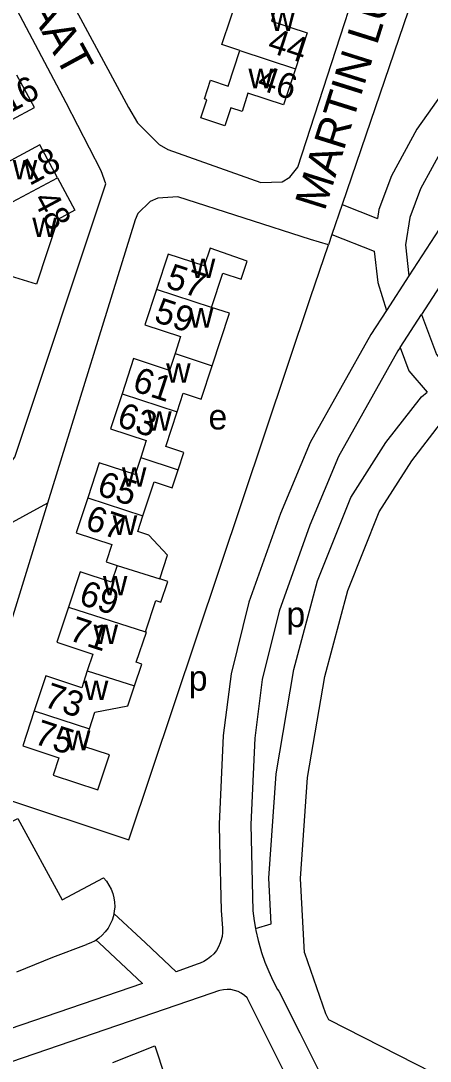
# Model space of a CAD drawing. Extents: x 157794 to 159375, y 380877 to 382306.
# Drawn here: x 159054.3 to 159118.9, y 381731.3 to 381895.6 of the extents above; entities that cross this region are included whole.
import ezdxf

# ---------------------------------------------------------------- set-up
doc = ezdxf.new("R2010")
doc.units = 0
for name, color, linetype in [('BLT_Basislijn', 7, 'Continuous'), ('BLT_Bebouwing', 7, 'Continuous'), ('BLT_Centroide', 7, 'Continuous'), ('BLT_Huisnummer', 7, 'Continuous'), ('BLT_Huisnummer_ tussenligend', 7, 'Continuous'), ('BLT_Onderverdeling_panden', 7, 'Continuous'), ('BLT_Straatnaam', 7, 'Continuous')]:
    doc.layers.add(name, color=color, linetype=linetype)

msp = doc.modelspace()

# ---------------------------------------------------------------- linework, layer by layer
at = {"layer": 'BLT_Basislijn'}
for p, q in [((159131.04, 381942.86), (159105.03, 381866.63)), ((159105.03, 381866.63), (159103.41, 381861.89)), ((159105.03, 381866.63), (159110.6, 381864.42)), ((159103.41, 381861.89), (159102.86, 381860.28)), ((159103.41, 381861.89), (159110.09, 381859.24)), ((159115.55, 381855.37), (159112.01, 381849.89)), ((159114.17, 381844.04), (159117.55, 381849.26)), ((159058.47, 381819.44), (159047.17, 381813.34)), ((159045.25, 381774.98), (159071.3, 381766.29)), ((159068.97, 381754.68), (159073.96, 381750)), ((159091.33, 381752.31), (159093.8, 381753.02)), ((159059.32, 381747.74), (159064.64, 381749.75)), ((159065.3, 381750), (159064.64, 381749.75)), ((159066.15, 381750.47), (159066.65, 381750)), ((159066.65, 381750), (159073.46, 381743.61)), ((159073.96, 381750), (159078.81, 381745.44)), ((159053.63, 381745.42), (159059.32, 381747.74)), ((159082.12, 381746.66), (159078.81, 381745.44)), ((159073.46, 381743.61), (158994.46, 381716.52)), ((159068.77, 381731.14), (159075.44, 381733.75))]:
    msp.add_line(p, q, dxfattribs=at)
for points in [[(159024.73, 381972.06), (159024.29, 381971.41), (159023.98, 381970.76), (159023.95, 381970.05), (159024.07, 381969.44), (159071.25, 381881.93), (159072.69, 381879.52), (159076.12, 381876.12), (159077.49, 381875.32), (159092.19, 381870.11), (159095.54, 381870.21), (159096.74, 381870.93), (159098.02, 381872.52), (159100, 381878.71), (159111.44, 381913.93), (159114.91, 381926.43), (159120.96, 381946.35)], [(158994.07, 381923.44), (158982.1, 381906.19), (158981.46, 381904.6), (158981.34, 381899.92), (158982.25, 381897.5), (159026.42, 381815.66), (159028.37, 381813.47), (159029.25, 381813.04), (159032.7, 381813.07), (159049.22, 381822.15), (159051.23, 381824.01), (159053.32, 381826.75), (159067.69, 381869.91), (159066.93, 381871.95), (159061.42, 381882.67), (159029.46, 381943.09)], [(159128.38, 381896.12), (159126.57, 381892.41), (159123.16, 381887.51), (159116.8, 381878.51), (159112.81, 381871.18), (159110.82, 381865.87), (159110.6, 381864.42)], [(159132.83, 381893.83), (159130.9, 381889.87), (159127.26, 381884.64), (159121.05, 381875.86), (159117.37, 381869.09), (159115.68, 381864.59), (159115.01, 381860.27), (159115.55, 381855.37)], [(159134.86, 381888.8), (159128.5, 381875.17), (159120.33, 381862.74), (159115.55, 381855.37)], [(159139.39, 381886.69), (159132.88, 381872.73), (159124.51, 381860.01), (159117.55, 381849.26)], [(159102.86, 381860.28), (159100, 381861.13), (159079.08, 381867.85), (159075.89, 381867.66), (159074.69, 381867.11), (159072.76, 381865.19), (159072.3, 381864.19), (159058.47, 381819.44)], [(159071.3, 381766.29), (159100, 381851.94), (159102.86, 381860.28)], [(159110.09, 381859.24), (159110.64, 381854.29), (159112.01, 381849.89)], [(159112.01, 381849.89), (159109.55, 381846.11), (159099.94, 381829.05), (159095.27, 381817.81), (159090.3, 381803.83), (159087.48, 381792.53), (159086.22, 381782.78), (159085.6, 381768.79), (159085.66, 381765.88)], [(159117.55, 381849.26), (159119.92, 381842.95), (159122.4, 381840.03)], [(159114.17, 381844.04), (159113.83, 381843.52), (159104.45, 381826.85), (159099.93, 381816.01), (159095.09, 381802.38), (159092.4, 381791.6), (159091.21, 381782.35), (159090.6, 381768.73), (159090.93, 381755.09)], [(159114.17, 381844.04), (159115.55, 381840.37), (159118.44, 381836.98)], [(159093.8, 381753.02), (159093.41, 381760.23), (159094.57, 381776.73), (159097.41, 381793.18), (159101.14, 381807.22), (159106.37, 381820.37), (159111.94, 381829.04), (159117.53, 381836.27), (159118.44, 381836.98)], [(159099.06, 381748.46), (159098.42, 381760.19), (159099.54, 381776.13), (159102.3, 381792.11), (159105.9, 381805.65), (159110.84, 381818.08), (159116.03, 381826.15), (159121.09, 381832.71), (159121.73, 381833.2)], [(159058.47, 381819.44), (159051.31, 381796.18), (159045.25, 381774.98)], [(159046.43, 381770.08), (159048.11, 381766.89), (159053.77, 381769.64), (159060.82, 381756.79), (159067.33, 381760.29)], [(159085.66, 381765.88), (159085.91, 381755.15), (159086.11, 381752.33)], [(159067.33, 381760.29), (159067.79, 381759.74), (159068.19, 381759.14), (159068.52, 381758.51), (159068.78, 381757.84), (159068.96, 381757.14), (159069.06, 381756.43), (159069.09, 381755.72), (159069.03, 381755), (159068.97, 381754.68)], [(159068.97, 381754.68), (159068.9, 381754.3), (159068.68, 381753.61), (159068.4, 381752.96), (159068.04, 381752.34), (159067.61, 381751.76), (159067.12, 381751.24), (159066.58, 381750.77), (159066.15, 381750.47)], [(159090.93, 381755.09), (159091.13, 381753.51), (159091.33, 381752.31)], [(159086.11, 381752.33), (159086.11, 381751.66), (159086.04, 381751), (159085.88, 381750.36), (159085.76, 381750)], [(159091.33, 381752.31), (159091.4, 381751.95), (159091.75, 381750.39), (159091.85, 381750)], [(159066.15, 381750.47), (159065.99, 381750.36), (159065.3, 381750)], [(159085.76, 381750), (159085.49, 381749.4), (159085.15, 381748.83), (159084.74, 381748.3), (159084.27, 381747.84), (159083.75, 381747.43), (159083.18, 381747.08), (159082.58, 381746.81), (159082.12, 381746.66)], [(159091.85, 381750), (159092.3, 381748.48), (159092.82, 381746.98), (159093.42, 381745.5), (159094.09, 381744.06), (159094.83, 381742.66), (159095, 381742.37)], [(159099.06, 381748.46), (159102.37, 381738.87), (159102.86, 381737.9)], [(159108.87, 381686.54), (159105.46, 381699.16), (159100.87, 381714.75), (159096.96, 381727.42), (159090, 381741.34), (159089.57, 381741.73), (159089.09, 381742.06), (159088.58, 381742.33), (159088.02, 381742.52), (159087.45, 381742.63), (159086.87, 381742.66), (159086.29, 381742.62), (159085.72, 381742.49), (159085.49, 381742.42), (159084.45, 381742.09), (158998.68, 381712.68), (159004.91, 381698.37), (159013.56, 381679.97)], [(159095, 381742.37), (159098.32, 381735.79)], [(159102.86, 381737.9), (159116.59, 381730.9), (159127, 381725.59), (159133.66, 381723.61), (159143.59, 381722.37), (159147.4, 381722.17)], [(159098.32, 381735.79), (159101.61, 381729.28), (159105.66, 381716.2), (159110.27, 381700.52), (159113.74, 381687.68)], [(159075.44, 381733.75), (159078.64, 381724.01)]]:
    msp.add_lwpolyline(points, dxfattribs=at)
at = {"layer": 'BLT_Bebouwing'}
for points in [[(159088.87, 381890.93), (159086.03, 381891.92), (159088.83, 381900.4)], [(159094.79, 381898.43), (159093.86, 381895.6), (159099.51, 381893.73), (159097.63, 381888.04)], [(159097.63, 381888.04), (159095.76, 381882.39), (159090.13, 381884.24), (159089.2, 381881.34), (159087.43, 381881.92), (159086.5, 381879.08), (159082.7, 381880.33), (159083.64, 381883.17), (159083.26, 381883.3), (159084.23, 381886.26), (159087.03, 381885.34), (159088.87, 381890.93)], [(159050.63, 381875.72), (159049.32, 381878.16), (159056.4, 381881.96), (159053.65, 381887.07)], [(159060.07, 381870.86), (159057.29, 381876.05), (159051.98, 381873.2), (159050.63, 381875.72)], [(159060.07, 381870.86), (159062.82, 381865.73), (159060.13, 381864.29), (159056.76, 381854.05), (159051.97, 381855.5), (159050.76, 381855.86), (159052.04, 381860.1), (159049.34, 381865.13)], [(159084.39, 381850.34), (159086.18, 381855.78), (159089.04, 381854.84), (159089.99, 381857.71), (159084.18, 381859.74), (159083.21, 381856.97), (159077.53, 381858.79), (159075.68, 381853.21)], [(159075.68, 381853.21), (159073.85, 381847.62), (159079.49, 381845.76), (159078.62, 381843.09)], [(159084.49, 381841.16), (159087.22, 381849.45), (159084.39, 381850.34)], [(159078.62, 381843.09), (159077.74, 381840.43), (159072.08, 381842.29), (159070.25, 381836.75)], [(159078.95, 381833.87), (159079.92, 381836.82), (159082.76, 381835.89), (159084.49, 381841.16)], [(159070.25, 381836.75), (159068.42, 381831.21), (159074.08, 381829.35), (159073.2, 381826.67)], [(159079.12, 381824.72), (159080.02, 381827.47), (159077.15, 381828.41), (159078.95, 381833.87)], [(159073.2, 381826.67), (159072.31, 381823.99), (159066.66, 381825.84), (159064.85, 381820.32)], [(159073.56, 381817.46), (159075.33, 381822.84), (159078.19, 381821.9), (159079.12, 381824.72)], [(159064.85, 381820.32), (159063.03, 381814.8), (159068.65, 381812.94), (159067.75, 381810.2), (159069.46, 381809.64)], [(159076.22, 381807.53), (159077.44, 381811.24), (159074.46, 381814.41), (159072.74, 381814.97), (159073.56, 381817.46)], [(159069.46, 381809.64), (159068.58, 381806.99), (159063.65, 381808.62), (159061.8, 381803.05)], [(159073.97, 381799.14), (159075.58, 381804.08), (159076.4, 381803.81), (159077.49, 381807.11), (159076.22, 381807.53)], [(159061.8, 381803.05), (159059.96, 381797.49), (159065.64, 381795.63), (159064.76, 381792.96)], [(159072.21, 381790.59), (159073.37, 381794.04), (159072.49, 381794.33), (159074.09, 381799.1), (159073.97, 381799.14)], [(159064.76, 381792.96), (159063.89, 381790.3), (159058.19, 381792.17), (159056.38, 381786.65)], [(159065.09, 381783.8), (159065.96, 381786.43), (159071.19, 381787.43), (159072.21, 381790.59)], [(159056.38, 381786.65), (159054.58, 381781.12), (159060.26, 381779.24), (159059.37, 381776.49), (159066.44, 381774.21), (159068.25, 381779.71), (159064.19, 381781.04), (159065.09, 381783.8)]]:
    msp.add_lwpolyline(points, dxfattribs=at)
at = {"layer": 'BLT_Onderverdeling_panden'}
for p, q in [((159088.87, 381890.93), (159097.63, 381888.04)), ((159049.34, 381865.13), (159060.07, 381870.86)), ((159084.39, 381850.34), (159075.68, 381853.21)), ((159078.62, 381843.09), (159084.49, 381841.16)), ((159070.25, 381836.75), (159078.95, 381833.87)), ((159073.2, 381826.67), (159079.12, 381824.72)), ((159064.85, 381820.32), (159073.56, 381817.46)), ((159069.46, 381809.64), (159076.22, 381807.53)), ((159061.8, 381803.05), (159073.97, 381799.14)), ((159064.76, 381792.96), (159072.21, 381790.59)), ((159056.38, 381786.65), (159065.09, 381783.8))]:
    msp.add_line(p, q, dxfattribs=at)

# ---------------------------------------------------------------- texts
at = {"layer": 'BLT_Centroide'}
for s, p in [('w', (159093.69, 381894.06)), ('w', (159090.22, 381885)), ('w', (159052.99, 381870.59)), ('w', (159056.08, 381861.48)), ('w', (159081.12, 381855.03)), ('w', (159080.81, 381847.19)), ('w', (159077.22, 381838.47)), ('w', (159074.22, 381830.89)), ('e', (159083.9, 381831.1)), ('w', (159070.24, 381822.06)), ('w', (159068.78, 381814.45)), ('w', (159067.23, 381804.91)), ('p', (159096.2, 381799.9)), ('w', (159065.75, 381797.2)), ('p', (159080.78, 381789.85)), ('w', (159064.23, 381788.38)), ('w', (159061.38, 381780.44))]:
    msp.add_text(s, height=4, dxfattribs=at).set_placement(p)
at = {"layer": 'BLT_Huisnummer'}
for s, rotation, p in [('46', 341.7416, (159091.4, 381884.95)), ('18', 28.2378, (159055.64, 381869.53)), ('48', 298.1888, (159056.1, 381867.46)), ('57', 341.7997, (159076.97, 381853.6)), ('61', 341.7997, (159071.71, 381837.27)), ('65', 341.7997, (159066.11, 381820.83)), ('69', 341.7997, (159063.25, 381803.58)), ('75', 341.7997, (159056.17, 381781.55))]:
    msp.add_text(s, height=4, rotation=rotation, dxfattribs=at).set_placement(p)
at = {"layer": 'BLT_Huisnummer_ tussenligend'}
for s, rotation, p in [('44', 341.7416, (159093.03, 381890.83)), ('16', 28.2378, (159052.27, 381880.86)), ('59', 341.7997, (159075.12, 381848.2)), ('63', 341.7997, (159069.26, 381831.68)), ('67', 341.7997, (159064.24, 381815.44)), ('71', 341.7997, (159061.67, 381797.88)), ('73', 341.7997, (159057.7, 381787.4))]:
    msp.add_text(s, height=4, rotation=rotation, dxfattribs=at).set_placement(p)
at = {"layer": 'BLT_Straatnaam'}
for s, rotation, p in [('MARTIN LUTHER KINGSTRAAT', 72.5304, (159102.24, 381865.46)), ('JAN PALACHSTRAAT', 298.5304, (159029.24, 381945.84))]:
    msp.add_text(s, height=5, rotation=rotation, dxfattribs=at).set_placement(p)

doc.saveas('drawing.dxf')
